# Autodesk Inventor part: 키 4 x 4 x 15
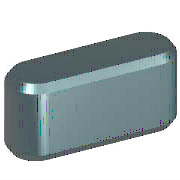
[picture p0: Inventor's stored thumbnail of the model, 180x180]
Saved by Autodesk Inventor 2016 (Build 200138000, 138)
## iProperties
IsCustomPart: 1
Created: 2012-02
Part Number: 키 4 x 4 x 15
Material: 강철, 연강
Description: 키 및 해당 키홈
Document SubType Name: Modeling
Standard: KS B 1311
Designer: test
Standards Organization: KS
Language: ko-KR
Size Designation: 4 x 4 x 10
Categories: <MemberInstance><Categories><Category DisplayName="샤프트 부품" InternalName="7f7aeb1f-a693-4053-b835-cee3144e0d98" Mnemonic="SHFT"><Category DisplayName="키" Interna
Density: 1 g/cm^3
Appearance: 노란색
Author: test
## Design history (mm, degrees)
workplane "Work Plane1"
workplane "Work Plane2"
sketch "스케치1"
  geometry: L1 (2, 2)-(13, 2); L2 (13, -2)-(2, -2); L3 (0, 8.8)-(0, -3.8) reference; L4 (-2, 0)-(12, 0) reference; L5 (15, 0)-(15, 7); A1 r 2 centre (2, 0) between (2, 2) and (2, -2); A2 r 2 centre (13, 0) between (13, -2) and (13, 2)
  constraints: 6 end point, 5 point on circle, 4 tangent, 3 point on line, 2 centre point, 1 horizontal, 1 parallel, 1 perpendicular
  dimensions: "d0" = 2 radius of A1 (= 0.5 x PB); "d13" = 2 radius of A2 (= 0.5 x PB); "d14" = 15 distance between parallel lines of L5 L3 (= NLG)
extrude "본체1" new body sketch "스케치1" taper "d3" = 0 deg; stored distance "d4" = 10
workplane "Work Plane3"
body "Solid1"
chamfer "모따기1" distance "d8" = 0.25 (= PHH); stored, may be unused: second distance "d9" = 0.25 (= PHH), angle "d15" = 45 deg
other parameters: "d1" = -2.5 (= -PNT), "d2" = 1.5 (= PH - PNT), "NLG" = 15 [user parameter; used in 3 equation terms], "PB" = 4 [user parameter; used in 2 equation terms], "PNT" = 2.5 [user parameter; used in 2 equation terms], "PH" = 4 [user parameter; used in 1 equation term], "PHH" = 0.25 [user parameter; used in 2 equation terms], "d10" = 0, "d16" = 0, "d17" = 0, "d18" = 0, "PLB2" = 15 (= NLG) [user parameter], "WDMAX" = 12 [user parameter], "PLB1" = 15 (= NLG) [user parameter], "RR" = 0.08 [user parameter], "PUEB" = 1.8 [user parameter]
